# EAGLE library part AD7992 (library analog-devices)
2-Channel, 12-Bit ADC with I2C-Compatible Interface 10-Lead MSOP Source: http://www.analog.com/UploadedFiles/Data_Sheets/224965274AD7992_0.pdf
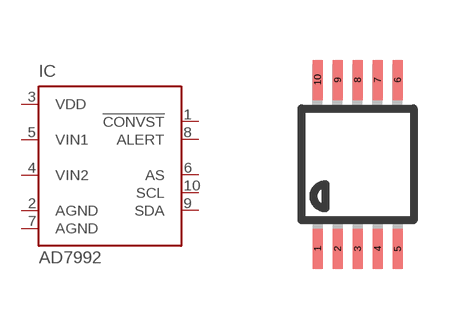
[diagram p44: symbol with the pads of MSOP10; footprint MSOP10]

Designator prefix IC

## AD7992 (MPN: AD7992BRMZ-0; OC_FARNELL: 1078311; OC_NEWARK: 31M4422)  [MSOP10]
1  !CONVST  in
2  AGND  pwr
3  VDD  pwr
4  VIN2  in
5  VIN1  in
6  AS  in
7  AGND  pwr
8  ALERT  out
9  SDA
10  SCL  in

## Footprint MSOP10 (pad centres in mm)
10-Lead Mini Small Outline Package [MSOP] (RM-10) Source: http://www.analog.com/UploadedFiles/Data_Sheets/35641221898805SSM2167_b.pdf COMPLIANT TO JEDEC STANDARDS MO-187BA
smd 0.25 x 1: 1 -1,-2.113; 2 -0.5,-2.113; 3 0,-2.113; 4 0.5,-2.113; 5 1,-2.113; 6 1,2.113; 7 0.5,2.113; 8 0,2.113; 9 -0.5,2.113; 10 -1,2.113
